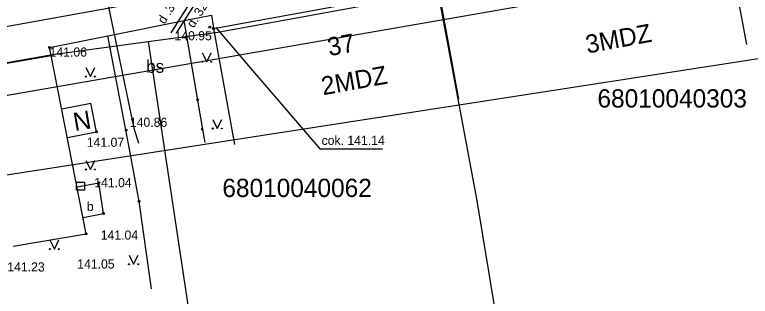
# Model space of a CAD drawing. Extents: x 728492 to 729038, y 272968 to 273171.
# Drawn here: x 728876.83 to 728917.09, y 273091.6 to 273107.02 of the extents above; entities that cross this region are included whole.
import ezdxf

# ---------------------------------------------------------------- set-up
doc = ezdxf.new("R2010")
doc.units = 0
for name, color, linetype in [('APGR_SARK_####_####_#', 7, 'Continuous'), ('BUVE_BDET_####_####_#', 7, 'Continuous'), ('BUVE_BDET_####_TKST_#', 7, 'Continuous'), ('BUVE_EKAS_####_####_#', 7, 'Continuous'), ('BUVE_EKAS_ADRS_TKST_#', 7, 'Continuous'), ('BUVE_EKAS_BPAL_####_#', 7, 'Continuous'), ('BUVE_EKAS_RAKS_TKST_#', 7, 'Continuous'), ('CELI_CAPM_####_####_#', 7, 'Continuous'), ('CELI_CMAL_####_####_#', 7, 'Continuous'), ('CELI_CSEG_####_TKST_#', 7, 'Continuous'), ('CELI_SEGL_####_####_#', 7, 'Continuous'), ('ELEK_ELEM_####_####_#', 7, 'Continuous'), ('ELEK_VADP_ZSPR_####_I', 7, 'Continuous'), ('Level 58', 7, 'Continuous'), ('RAMI_UZMR_####_####_#', 7, 'Continuous'), ('RELJ_AATZ_####_TKST_#', 7, 'Continuous'), ('RELJ_ELEM_####_####_#', 7, 'Continuous'), ('ROBZ_KADS_####_TKST_#', 7, 'Continuous'), ('ROBZ_UZMR_####_####_#', 7, 'Continuous'), ('TERT_ELEM_####_####_#', 7, 'Continuous'), ('UDTK_VADP_UDEN_####_#', 7, 'Continuous'), ('UDTK_VADP_UDEN_TKST_#', 7, 'Continuous')]:
    doc.layers.add(name, color=color, linetype=linetype)

msp = doc.modelspace()

# ---------------------------------------------------------------- linework, layer by layer
at = {"layer": 'APGR_SARK_####_####_#'}
msp.add_lwpolyline([(728964.826, 273117.961), (728827.017, 273094.024)], dxfattribs=at)
at = {"layer": 'BUVE_BDET_####_####_#'}
for p, q in [((728880.242, 273097.588), (728881.436, 273097.823)), ((728881.696, 273096.131), (728881.436, 273097.823)), ((728880.572, 273095.91), (728881.696, 273096.131))]:
    msp.add_line(p, q, dxfattribs=at)
for points in [[(728887.835, 273106.309), (728889.733, 273104.097)], [(728889.733, 273104.097), (728893.529, 273099.671), (728896.967, 273099.671)]]:
    msp.add_lwpolyline(points, dxfattribs=at)
at = {"layer": 'BUVE_EKAS_####_####_#'}
for p, q in [((728887.713, 273106.266), (728899.988, 273108.511)), ((728899.988, 273108.511), (728900.529, 273105.597)), ((728916.909, 273105.391), (728916.442, 273107.808)), ((728887.713, 273106.266), (728888.863, 273099.921)), ((728900.529, 273105.597), (728901.124, 273102.392)), ((728865.753, 273102.512), (728878.827, 273104.792))]:
    msp.add_line(p, q, dxfattribs=at)
msp.add_lwpolyline([(728876.752, 273094.355), (728880.747, 273095.017), (728878.827, 273104.792)], dxfattribs=at)
at = {"layer": 'BUVE_EKAS_BPAL_####_#'}
for p, q in [((728879.403, 273101.859), (728880.994, 273102.172)), ((728881.302, 273100.605), (728880.994, 273102.172)), ((728879.711, 273100.292), (728881.302, 273100.605))]:
    msp.add_line(p, q, dxfattribs=at)
at = {"layer": 'CELI_CAPM_####_####_#'}
msp.add_lwpolyline([(728921.451, 273114.43), (728906.807, 273111.886), (728887.177, 273108.316), (728871.777, 273105.534), (728862.513, 273103.854), (728851.375, 273101.928), (728832.719, 273098.413), (728826.071, 273097.316), (728825.017, 273097.001), (728824.765, 273096.832), (728824.532, 273096.455), (728824.532, 273096.455), (728826.161, 273084.877), (728827.609, 273074.269)], dxfattribs=at)
at = {"layer": 'CELI_CMAL_####_####_#'}
for p, q in [((728886.101, 273106.695), (728887.595, 273106.994)), ((728887.595, 273106.994), (728887.713, 273106.266)), ((728878.739, 273105.225), (728881.926, 273105.862)), ((728878.827, 273104.792), (728878.739, 273105.225)), ((728882.066, 273105.128), (728882.027, 273105.331)), ((728887.245, 273100.022), (728887.123, 273100.733))]:
    msp.add_line(p, q, dxfattribs=at)
for points in [[(728887.123, 273100.733), (728886.101, 273106.695)], [(728884.323, 273092.016), (728883.636, 273096.797), (728883.11, 273099.655), (728881.926, 273105.862)]]:
    msp.add_lwpolyline(points, dxfattribs=at)
at = {"layer": 'CELI_SEGL_####_####_#'}
msp.add_line((728881.926, 273105.862), (728886.101, 273106.695), dxfattribs=at)
at = {"layer": 'ELEK_ELEM_####_####_#'}
msp.add_lwpolyline([(728880.651, 273097.407), (728880.204, 273097.407), (728880.204, 273097.847), (728880.651, 273097.847)], close=True, dxfattribs=at)
at = {"layer": 'ELEK_VADP_ZSPR_####_I'}
for p, q in [((728879.197, 273120.548), (728883.359, 273100.8)), ((728883.359, 273100.8), (728883.604, 273099.978))]:
    msp.add_line(p, q, dxfattribs=at)
at = {"layer": 'Level 58'}
msp.add_line((728887.114, 273100.7), (728887.138, 273100.788), dxfattribs=at)
msp.add_arc((728887.107, 273100.749), 0.05, 51.062, 277.5227, dxfattribs=at)
at = {"layer": 'RAMI_UZMR_####_####_#'}
msp.add_lwpolyline([(728688.721, 273058.407), (728702.149, 273066.922), (728733.452, 273072.937), (728813.127, 273088.247), (728815.181, 273072.879), (728831.342, 273076.994), (728831.817, 273091.35), (728930.137, 273106.573), (728962.389, 273111.567), (728966.363, 273103.835), (728988.796, 273109.153), (728985.811, 273141.417), (728955.146, 273144.603), (728957.616, 273137.975), (728904.333, 273130.641), (728847.677, 273120.095), (728823.483, 273119.793), (728790.036, 273112.558), (728726.814, 273102.175), (728686.914, 273096.216)], dxfattribs=at)
at = {"layer": 'RELJ_ELEM_####_####_#'}
for centre in [(728887.509, 273106.337), (728887.713, 273106.266), (728878.739, 273105.225), (728886.844, 273102.362), (728882.925, 273100.702), (728881.302, 273100.605), (728881.302, 273100.605), (728881.436, 273097.823), (728881.436, 273097.823), (728883.636, 273096.797), (728881.696, 273096.131), (728880.747, 273095.017)]:
    msp.add_circle(centre, 0.05, dxfattribs=at)
at = {"layer": 'ROBZ_UZMR_####_####_#'}
for p, q in [((728887.944, 273106.064), (728900.011, 273108.272)), ((728902.123, 273096.935), (728900.011, 273108.272)), ((728884.133, 273105.553), (728887.944, 273106.064)), ((728878.892, 273104.843), (728884.133, 273105.553)), ((728884.133, 273105.553), (728887.23, 273085.057)), ((728865.791, 273102.548), (728878.892, 273104.843)), ((728903.503, 273088.609), (728902.123, 273096.935))]:
    msp.add_line(p, q, dxfattribs=at)
at = {"layer": 'TERT_ELEM_####_####_#'}
for p, q in [((728887.091, 273104.94), (728887.341, 273104.44)), ((728887.341, 273104.44), (728887.591, 273104.94)), ((728880.721, 273104.131), (728880.971, 273103.631)), ((728880.971, 273103.631), (728881.221, 273104.131)), ((728887.666, 273101.289), (728887.916, 273100.789)), ((728887.916, 273100.789), (728888.166, 273101.289)), ((728880.721, 273099.044), (728880.971, 273098.544)), ((728880.971, 273098.544), (728881.221, 273099.044)), ((728878.75, 273094.686), (728879, 273094.186)), ((728879, 273094.186), (728879.25, 273094.686)), ((728883.086, 273093.856), (728883.336, 273093.356)), ((728883.336, 273093.356), (728883.586, 273093.856))]:
    msp.add_line(p, q, dxfattribs=at)
for centre, radius in [((728887.091, 273104.439), 0.028), ((728887.591, 273104.439), 0.0263), ((728880.721, 273103.63), 0.028), ((728881.221, 273103.63), 0.0263), ((728887.666, 273100.788), 0.028), ((728888.166, 273100.788), 0.0263), ((728880.721, 273098.544), 0.028), ((728881.221, 273098.544), 0.0263), ((728878.749, 273094.186), 0.028), ((728879.249, 273094.186), 0.0263), ((728883.086, 273093.356), 0.028), ((728883.586, 273093.356), 0.0263)]:
    msp.add_circle(centre, radius, dxfattribs=at)
at = {"layer": 'UDTK_VADP_UDEN_####_#'}
for p, q in [((728887.904, 273110.027), (728885.366, 273106.022)), ((728885.681, 273106), (728888.252, 273110.087))]:
    msp.add_line(p, q, dxfattribs=at)

# ---------------------------------------------------------------- texts
at = {"layer": 'BUVE_BDET_####_TKST_#'}
for s, height, p in [('cok. 141.14', 0.49999, (728893.626, 273099.889)), ('b', 0.5, (728880.779, 273096.27))]:
    msp.add_text(s, height=height, dxfattribs=at).set_placement(p)
at = {"layer": 'BUVE_EKAS_ADRS_TKST_#'}
msp.add_text('37', height=1, rotation=10.27, dxfattribs=at).set_placement((728894.049, 273104.748))
at = {"layer": 'BUVE_EKAS_RAKS_TKST_#'}
for s, rotation, p in [('3MDZ', 10.515, (728908.175, 273104.887)), ('2MDZ', 10.27, (728893.707, 273102.605)), ('N', 9.893, (728880.124, 273100.64))]:
    msp.add_text(s, height=1, rotation=rotation, dxfattribs=at).set_placement(p)
at = {"layer": 'CELI_CSEG_####_TKST_#'}
msp.add_text('bs', height=0.7, dxfattribs=at).set_placement((728884.023, 273103.839))
at = {"layer": 'RELJ_AATZ_####_TKST_#'}
for s, p in [('140.95', (728885.574, 273105.615)), ('141.06', (728878.739, 273104.725)), (' 140.86', (728882.947, 273100.879)), (' 141.07', (728880.589, 273099.785)), (' 141.04', (728880.999, 273097.576)), (' 141.04', (728881.352, 273094.707)), (' 141.23', (728876.24, 273092.961)), (' 141.05', (728880.065, 273093.121))]:
    msp.add_text(s, height=0.5, dxfattribs=at).set_placement(p)
at = {"layer": 'ROBZ_KADS_####_TKST_#'}
for s, p in [('68010040303', (728908.725, 273101.937)), ('68010040062', (728888.195, 273097.037))]:
    msp.add_text(s, height=1, dxfattribs=at).set_placement(p)
at = {"layer": 'UDTK_VADP_UDEN_TKST_#'}
for s, rotation, p in [('d .32', 57.8304, (728885.03, 273106.47)), ('d. 32', 57.6331, (728886.622, 273106.258))]:
    msp.add_text(s, height=0.5, rotation=rotation, dxfattribs=at).set_placement(p)

doc.saveas('drawing.dxf')
